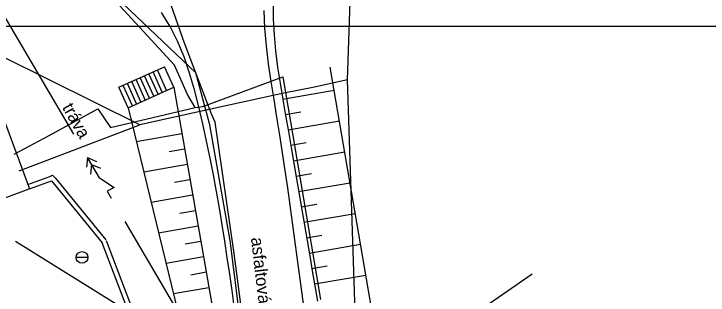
# Model space of a CAD drawing. Extents: x -614582 to -612559, y -1157748 to -1156203.
# Drawn here: x -613976.51 to -613932.06, y -1156760.22 to -1156742.23 of the extents above; entities that cross this region are included whole.
import ezdxf

# ---------------------------------------------------------------- set-up
doc = ezdxf.new("R2010")
doc.units = 0
for name, color, linetype in [('Vrstva 12', 7, 'Continuous'), ('Vrstva 13', 7, 'Continuous'), ('Vrstva 15', 7, 'Continuous'), ('Vrstva 17', 7, 'Continuous'), ('Vrstva 20', 7, 'Continuous'), ('Vrstva 34', 7, 'Continuous'), ('Vrstva 4', 7, 'Continuous'), ('Vrstva 47', 7, 'Continuous'), ('Vrstva 5', 7, 'Continuous'), ('Vrstva 60', 7, 'Continuous'), ('Vrstva 9', 7, 'Continuous')]:
    doc.layers.add(name, color=color, linetype=linetype)

# ---------------------------------------------------------------- blocks, each defined once
blk = doc.blocks.new('SC3404')
at = {"layer": 'Vrstva 9'}
blk.add_lwpolyline([(3.75, 0), (-3.75, 0)], dxfattribs=at)
blk.add_circle((0, 0), 3.75, dxfattribs=at)
blk = doc.blocks.new('SC3413')
at = {"layer": 'Vrstva 15'}
for points in [[(0, -0.625), (-10, 4.375), (-10, -0.625), (-15, -0.625)], [(10, -0.625), (5, 3.125)], [(15, -0.625), (10, 3.125)], [(0, -0.625), (15, -0.625), (10, -4.375)], [(15, -0.625), (10, -0.625), (5, -4.375)]]:
    blk.add_lwpolyline(points, dxfattribs=at)

msp = doc.modelspace()

# ---------------------------------------------------------------- linework, layer by layer
at = {"layer": 'Vrstva 12'}
for p, q in [((-613959.306, -1156747.678), (-613956.003, -1156747.105)), ((-613959.133, -1156748.663), (-613958.144, -1156748.488)), ((-613958.96, -1156749.648), (-613955.667, -1156749.072)), ((-613968.675, -1156750.382), (-613965.758, -1156749.87)), ((-613958.788, -1156750.633), (-613957.798, -1156750.461)), ((-613966.575, -1156751.029), (-613965.585, -1156750.855)), ((-613958.618, -1156751.618), (-613955.328, -1156751.052)), ((-613968.199, -1156752.329), (-613965.412, -1156751.84)), ((-613958.449, -1156752.604), (-613957.458, -1156752.434)), ((-613966.23, -1156752.999), (-613965.24, -1156752.825)), ((-613958.28, -1156753.59), (-613954.99, -1156753.028)), ((-613967.724, -1156754.276), (-613965.067, -1156753.81)), ((-613958.112, -1156754.576), (-613957.121, -1156754.407)), ((-613965.884, -1156754.969), (-613964.894, -1156754.795)), ((-613957.944, -1156755.561), (-613954.653, -1156755)), ((-613967.248, -1156756.223), (-613964.721, -1156755.78)), ((-613957.776, -1156756.547), (-613956.785, -1156756.378)), ((-613965.539, -1156756.939), (-613964.549, -1156756.765)), ((-613957.607, -1156757.533), (-613954.317, -1156756.968)), ((-613966.773, -1156758.17), (-613964.376, -1156757.75)), ((-613957.437, -1156758.518), (-613956.447, -1156758.347)), ((-613965.193, -1156758.909), (-613964.203, -1156758.735)), ((-613957.266, -1156759.504), (-613953.981, -1156758.931)), ((-613966.298, -1156760.118), (-613964.031, -1156759.72))]:
    msp.add_line(p, q, dxfattribs=at)
at = {"layer": 'Vrstva 15'}
for p, q in [((-613972.684, -1156749.913), (-613977.891, -1156741.056)), ((-613964.184, -1156764.373), (-613969.39, -1156755.517))]:
    msp.add_line(p, q, dxfattribs=at)
at = {"layer": 'Vrstva 17'}
for p, q in [((-613965.691, -1156743.806), (-613967.791, -1156737.826)), ((-613955.161, -1156746.456), (-613954.971, -1156741.456)), ((-613965.411, -1156744.556), (-613965.691, -1156743.806)), ((-613964.111, -1156747.966), (-613965.411, -1156744.556)), ((-613968.441, -1156749.316), (-613977.181, -1156744.986)), ((-613955.161, -1156746.456), (-613957.381, -1156746.936)), ((-613954.521, -1156765.786), (-613955.161, -1156746.456)), ((-613959.221, -1156747.296), (-613964.001, -1156748.346)), ((-613957.381, -1156746.936), (-613959.221, -1156747.296)), ((-613963.841, -1156748.686), (-613964.111, -1156747.966)), ((-613964.001, -1156748.346), (-613968.441, -1156749.316)), ((-613963.631, -1156749.156), (-613963.841, -1156748.686)), ((-613976.181, -1156752.276), (-613968.441, -1156749.316)), ((-613962.411, -1156757.556), (-613963.631, -1156749.156)), ((-613961.361, -1156765.406), (-613962.411, -1156757.556))]:
    msp.add_line(p, q, dxfattribs=at)
at = {"layer": 'Vrstva 20'}
for p, q in [((-613964.872, -1156746.001), (-613971.901, -1156739.295)), ((-613964.872, -1156746.001), (-613971.901, -1156739.295)), ((-613964.872, -1156746.001), (-613971.901, -1156739.295)), ((-613964.872, -1156746.001), (-613971.901, -1156739.295)), ((-613963.976, -1156749.318), (-613964.872, -1156746.001)), ((-613963.976, -1156749.318), (-613964.872, -1156746.001)), ((-613963.976, -1156749.318), (-613964.872, -1156746.001)), ((-613963.976, -1156749.318), (-613964.872, -1156746.001)), ((-613962.673, -1156756.726), (-613963.976, -1156749.318)), ((-613962.673, -1156756.726), (-613963.976, -1156749.318)), ((-613962.673, -1156756.726), (-613963.976, -1156749.318)), ((-613962.673, -1156756.726), (-613963.976, -1156749.318)), ((-613960.838, -1156771.049), (-613962.673, -1156756.726)), ((-613960.838, -1156771.049), (-613962.673, -1156756.726)), ((-613960.838, -1156771.049), (-613962.673, -1156756.726)), ((-613960.838, -1156771.049), (-613962.673, -1156756.726))]:
    msp.add_line(p, q, dxfattribs=at)
at = {"layer": 'Vrstva 34'}
msp.add_line((-613964.184, -1156764.373), (-613976.415, -1156756.796), dxfattribs=at)
at = {"layer": 'Vrstva 4'}
for p, q in [((-613969.787, -1156746.92), (-613966.867, -1156745.61)), ((-613967.011, -1156747.244), (-613967.597, -1156745.938)), ((-613967.011, -1156747.244), (-613967.597, -1156745.938)), ((-613966.737, -1156747.121), (-613967.323, -1156745.815)), ((-613966.281, -1156746.916), (-613966.867, -1156745.61)), ((-613953.061, -1156764.316), (-613956.254, -1156745.637)), ((-613968.106, -1156747.735), (-613968.692, -1156746.429)), ((-613967.832, -1156747.612), (-613968.418, -1156746.306)), ((-613967.559, -1156747.49), (-613968.144, -1156746.184)), ((-613967.285, -1156747.367), (-613967.871, -1156746.061)), ((-613969.201, -1156748.226), (-613969.787, -1156746.92)), ((-613968.927, -1156748.104), (-613969.513, -1156746.798)), ((-613968.653, -1156747.981), (-613969.239, -1156746.675)), ((-613969.201, -1156748.226), (-613966.281, -1156746.916)), ((-613968.38, -1156747.858), (-613968.966, -1156746.552)), ((-613966.281, -1156746.916), (-613963.221, -1156764.366)), ((-613977.651, -1156747.666), (-613975.517, -1156753.423)), ((-613969.201, -1156748.226), (-613965.021, -1156765.346)), ((-613975.621, -1156753.141), (-613974.215, -1156752.62)), ((-613974.215, -1156752.62), (-613974.043, -1156752.554)), ((-613973.879, -1156752.711), (-613974.043, -1156752.554)), ((-613975.517, -1156753.423), (-613974.111, -1156752.901)), ((-613974.111, -1156752.901), (-613970.86, -1156756.872)), ((-613973.879, -1156752.711), (-613970.628, -1156756.682)), ((-613975.888, -1156753.56), (-613978.514, -1156754.533)), ((-613975.517, -1156753.423), (-613975.888, -1156753.56)), ((-613943.325, -1156758.868), (-613950.821, -1156764.056))]:
    msp.add_line(p, q, dxfattribs=at)
for points in [[(-613959.901, -1156741.563), (-613959.907, -1156742.561), (-613959.857, -1156743.574), (-613959.761, -1156744.598), (-613959.629, -1156745.63), (-613959.471, -1156746.665), (-613959.297, -1156747.699), (-613959.116, -1156748.729), (-613958.937, -1156749.751), (-613958.76, -1156750.766), (-613958.586, -1156751.774), (-613958.415, -1156752.774), (-613958.245, -1156753.769), (-613958.076, -1156754.758), (-613957.908, -1156755.741), (-613957.741, -1156756.72), (-613957.574, -1156757.695), (-613957.407, -1156758.666), (-613957.239, -1156759.633), (-613957.07, -1156760.599)], [(-613957.923, -1156761.072), (-613958.07, -1156759.979), (-613958.217, -1156758.883), (-613958.365, -1156757.784), (-613958.514, -1156756.683), (-613958.666, -1156755.577), (-613958.822, -1156754.468), (-613958.981, -1156753.354), (-613959.144, -1156752.235), (-613959.313, -1156751.11), (-613959.488, -1156749.98), (-613959.669, -1156748.844), (-613959.856, -1156747.702), (-613960.038, -1156746.556), (-613960.203, -1156745.412), (-613960.341, -1156744.271), (-613960.438, -1156743.137), (-613960.484, -1156742.015)], [(-613962.4, -1156760.952), (-613962.544, -1156759.912), (-613962.693, -1156758.869), (-613962.848, -1156757.823), (-613963.009, -1156756.773), (-613963.178, -1156755.718), (-613963.355, -1156754.659), (-613963.543, -1156753.595), (-613963.74, -1156752.524), (-613963.95, -1156751.447), (-613964.172, -1156750.363), (-613964.408, -1156749.27), (-613964.662, -1156748.175), (-613964.942, -1156747.086), (-613965.258, -1156746.016), (-613965.618, -1156744.975), (-613966.031, -1156743.975), (-613966.508, -1156743.026), (-613967.055, -1156742.14)]]:
    msp.add_lwpolyline(points, dxfattribs=at)
at = {"layer": 'Vrstva 47'}
for p, q in [((-613966.231, -1156745.507), (-613970.786, -1156740.549)), ((-613965.397, -1156747.385), (-613966.231, -1156745.507)), ((-613964.412, -1156748.155), (-613959.293, -1156746.247)), ((-613959.293, -1156746.247), (-613958.659, -1156749.996)), ((-613964.907, -1156748.209), (-613965.397, -1156747.385)), ((-613970.331, -1156749.497), (-613964.907, -1156748.209)), ((-613964.907, -1156748.209), (-613964.412, -1156748.155)), ((-613974.262, -1156749.996), (-613971.145, -1156748.307)), ((-613971.145, -1156748.307), (-613970.331, -1156749.497)), ((-613976.491, -1156751.204), (-613974.262, -1156749.996)), ((-613976.491, -1156751.204), (-613974.262, -1156749.996)), ((-613958.659, -1156749.996), (-613956.884, -1156760.491)), ((-613958.659, -1156749.996), (-613956.884, -1156760.491))]:
    msp.add_line(p, q, dxfattribs=at)
at = {"layer": 'Vrstva 5'}
for p, q in [((-613967.081, -1156766.753), (-613970.86, -1156756.872)), ((-613966.801, -1156766.646), (-613970.591, -1156756.736))]:
    msp.add_line(p, q, dxfattribs=at)
at = {"layer": 'Vrstva 60'}
msp.add_line((-613903.789, -1156743.026), (-614043.789, -1156743.026), dxfattribs=at)

# ---------------------------------------------------------------- block references
at = {"layer": 'Vrstva 15', "xscale": 0.09999999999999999, "yscale": -0.1, "rotation": 120.44932687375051}
msp.add_blockref('SC3413', (-613970.983, -1156752.683), dxfattribs=at)
at = {"layer": 'Vrstva 9', "xscale": 0.1, "yscale": 0.10000000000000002}
msp.add_blockref('SC3404', (-613972.151, -1156757.806), dxfattribs=at)

# ---------------------------------------------------------------- texts
at = {"layer": 'Vrstva 13'}
for s, height, rotation, p in [('tráva', 0.8, 299.3737, (-613973.442, -1156748.208)), ('asfaltová cesta', 0.79999, 276.6569, (-613961.337, -1156756.561))]:
    msp.add_text(s, height=height, rotation=rotation, dxfattribs=at).set_placement(p)

doc.saveas('drawing.dxf')
